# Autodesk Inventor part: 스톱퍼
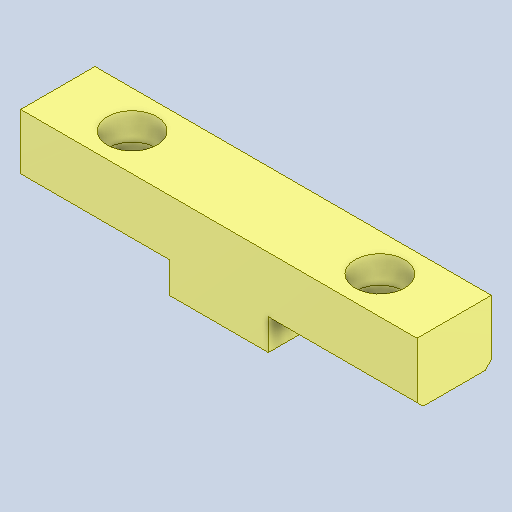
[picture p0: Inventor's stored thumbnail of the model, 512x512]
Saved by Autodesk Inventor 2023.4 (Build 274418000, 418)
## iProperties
Created: 2024-10
Part Number: 스톱퍼
Material: 강철, 연강
Document SubType Name: Modeling
Designer: EDU
Density: 7.85 g/cm^3
Appearance: 기본값
Author: jhkim
Sending System: Autodesk Inventor 2025
Preprocessor: ST-DEVELOPER v20
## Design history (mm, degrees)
feature "솔리드1"
node "솔리드2"
